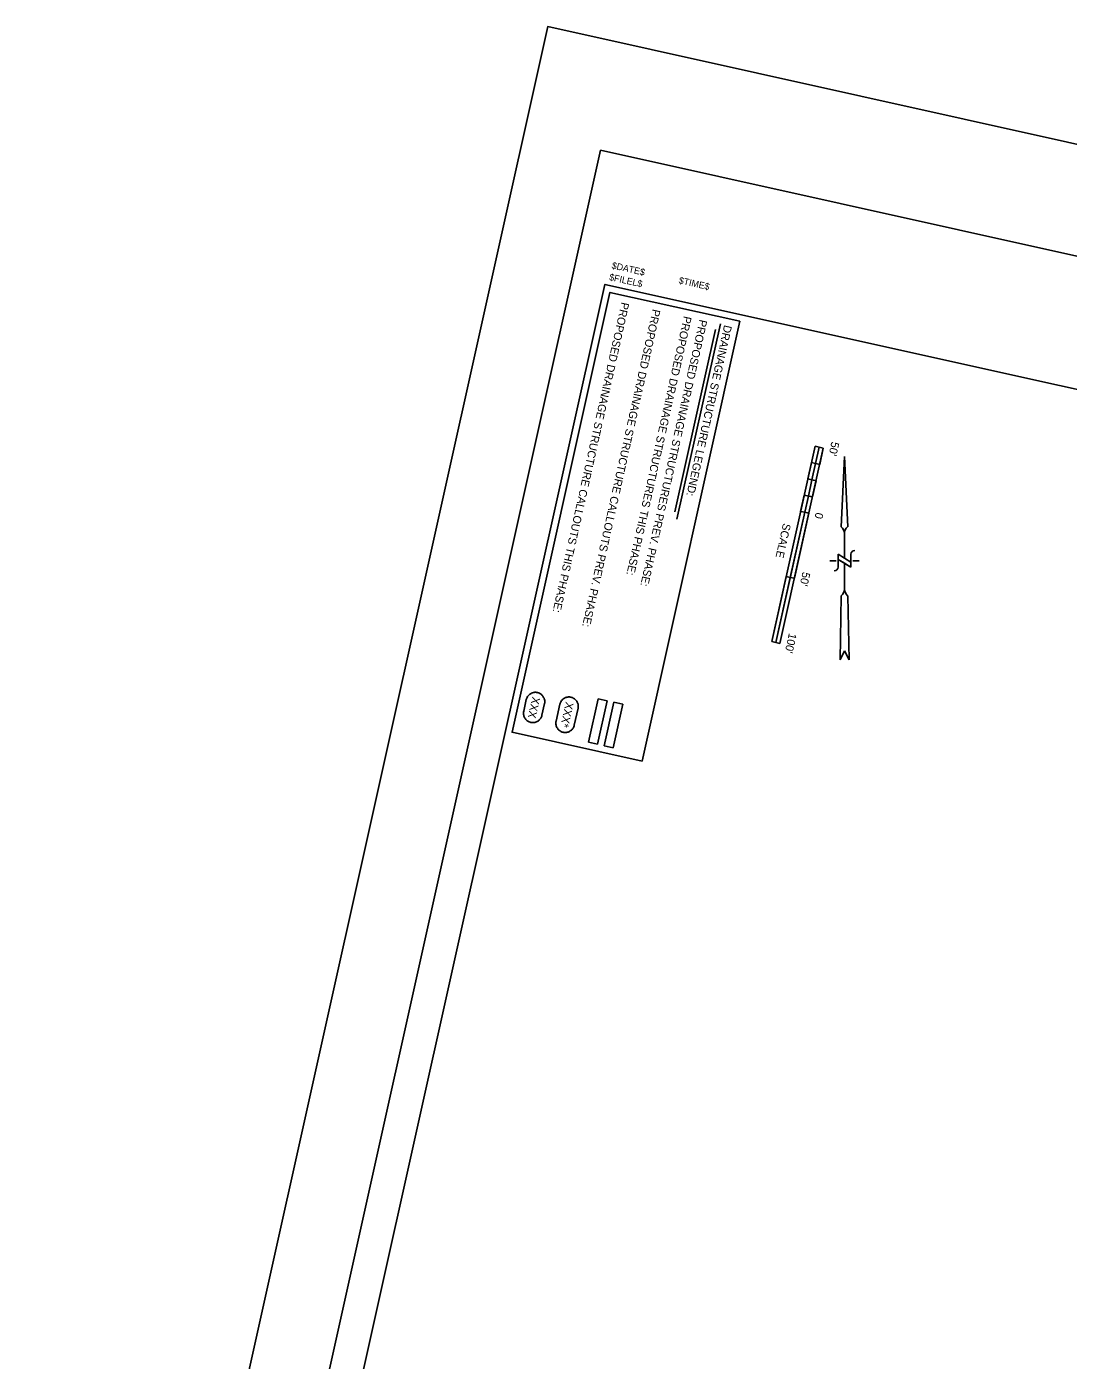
# Model space of a CAD drawing. Extents: x 2149822 to 2151384, y 143568 to 145586.
# Drawn here: x 2149822 to 2150603, y 144586 to 145586 of the extents above; entities that cross this region are included whole.
import ezdxf

# ---------------------------------------------------------------- set-up
doc = ezdxf.new("R2010")
doc.units = 0
for name, color, linetype in [('INR_Tracking', 7, 'Continuous'), ('PR_Storm_Conc_Drop_Inlet', 7, 'Continuous'), ('PR_Storm_Conc_Pipe', 7, 'Continuous'), ('PR_Storm_Conc_Pipe_PH1B', 7, 'Continuous'), ('PR_Storm_MH', 7, 'Continuous'), ('PR_Storm_Txt', 7, 'Continuous'), ('PR_Storm_Txt_PH1B', 7, 'Continuous'), ('SHT_Plot_Shape_Full', 7, 'Continuous'), ('SHT_Plot_Shape_Half', 7, 'Continuous'), ('SHT_Plot_Stamp', 7, 'Continuous')]:
    doc.layers.add(name, color=color, linetype=linetype)

msp = doc.modelspace()

# ---------------------------------------------------------------- linework, layer by layer
at = {"layer": 'INR_Tracking'}
msp.add_lwpolyline([(2149913.6, 143855.3), (2150255.5, 145392.7), (2151280.5, 145164.8), (2150938.6, 143627.3)], close=True, dxfattribs=at)
at = {"layer": 'PR_Storm_Conc_Drop_Inlet'}
for p, q in [((2150413.2, 145271.3), (2150380.6, 145124.9)), ((2150419.3, 145269.9), (2150386.7, 145123.5)), ((2150419.3, 145269.9), (2150413.2, 145271.3)), ((2150416.2, 145270.6), (2150413.5, 145258.4)), ((2150416.2, 145270.6), (2150413.5, 145258.4)), ((2150419.3, 145269.9), (2150416.2, 145270.6)), ((2150416.6, 145257.7), (2150419.3, 145269.9)), ((2150410.5, 145259.1), (2150407.8, 145246.9)), ((2150416.6, 145257.7), (2150410.5, 145259.1)), ((2150413.5, 145258.4), (2150410.5, 145259.1)), ((2150413.5, 145258.4), (2150410.8, 145246.2)), ((2150410.8, 145246.2), (2150413.5, 145258.4)), ((2150413.5, 145258.4), (2150416.6, 145257.7)), ((2150413.9, 145245.5), (2150407.8, 145246.9)), ((2150413.9, 145245.5), (2150407.8, 145246.9)), ((2150407.8, 145246.9), (2150410.8, 145246.2)), ((2150410.8, 145246.2), (2150408.1, 145234)), ((2150410.8, 145246.2), (2150408.1, 145234)), ((2150413.9, 145245.5), (2150410.8, 145246.2)), ((2150411.1, 145233.3), (2150413.9, 145245.5)), ((2150405, 145234.7), (2150402.3, 145222.5)), ((2150411.1, 145233.3), (2150405, 145234.7)), ((2150408.1, 145234), (2150405, 145234.7)), ((2150408.1, 145234), (2150405.4, 145221.8)), ((2150405.4, 145221.8), (2150408.1, 145234)), ((2150408.1, 145234), (2150411.1, 145233.3)), ((2150405.4, 145221.8), (2150383.7, 145124.2)), ((2150405.4, 145221.8), (2150394.5, 145173)), ((2150402.3, 145222.5), (2150405.4, 145221.8)), ((2150402.3, 145222.5), (2150405.4, 145221.8)), ((2150405.4, 145221.8), (2150408.4, 145221.1)), ((2150408.4, 145221.1), (2150405.4, 145221.8)), ((2150397.6, 145172.3), (2150408.4, 145221.1)), ((2150391.5, 145173.7), (2150380.6, 145124.9)), ((2150383.7, 145124.2), (2150394.5, 145173)), ((2150391.5, 145173.7), (2150394.5, 145173)), ((2150394.5, 145173), (2150391.5, 145173.7)), ((2150394.5, 145173), (2150397.6, 145172.3)), ((2150394.5, 145173), (2150397.6, 145172.3)), ((2150383.7, 145124.2), (2150380.6, 145124.9)), ((2150380.6, 145124.9), (2150383.7, 145124.2)), ((2150386.7, 145123.5), (2150383.7, 145124.2))]:
    msp.add_line(p, q, dxfattribs=at)
at = {"layer": 'PR_Storm_Conc_Pipe'}
for p, q in [((2150250.4, 145082), (2150243.2, 145049.3)), ((2150257.3, 145080.5), (2150250.4, 145082)), ((2150250, 145047.8), (2150257.3, 145080.5)), ((2150250, 145047.8), (2150243.2, 145049.3))]:
    msp.add_line(p, q, dxfattribs=at)
at = {"layer": 'PR_Storm_Conc_Pipe_PH1B'}
for p, q in [((2150262.2, 145079.4), (2150254.9, 145046.7)), ((2150261.7, 145045.1), (2150269, 145077.9)), ((2150269, 145077.9), (2150262.2, 145079.4)), ((2150261.7, 145045.1), (2150254.9, 145046.7))]:
    msp.add_line(p, q, dxfattribs=at)
at = {"layer": 'PR_Storm_MH'}
for p, q in [((2150432.8, 145210.8), (2150435.2, 145263.7)), ((2150435.2, 145263.7), (2150432.8, 145210.8)), ((2150435.2, 145263.7), (2150437.6, 145210.8)), ((2150437.6, 145210.8), (2150435.2, 145263.7)), ((2150435.2, 145187.4), (2150435.2, 145206.1)), ((2150428.9, 145185.5), (2150424.2, 145185.5)), ((2150440, 145184.5), (2150430.4, 145190.3)), ((2150430.4, 145190.3), (2150440, 145184.5)), ((2150430.4, 145190.3), (2150430.4, 145180.7)), ((2150435.2, 145187.4), (2150430.4, 145190.3)), ((2150430.4, 145190.3), (2150430.4, 145186.5)), ((2150440, 145180.7), (2150430.4, 145186.5)), ((2150440, 145184.5), (2150435.2, 145187.4)), ((2150435.2, 145163.9), (2150435.2, 145183.6)), ((2150440, 145190.3), (2150440, 145180.7)), ((2150440, 145180.7), (2150440, 145184.5)), ((2150446.2, 145185.5), (2150441.4, 145185.5)), ((2150431.9, 145111.1), (2150432.8, 145159.1)), ((2150432.8, 145159.1), (2150431.9, 145111.1)), ((2150438.6, 145111.1), (2150437.6, 145159.1)), ((2150438.6, 145111.1), (2150437.6, 145159.1)), ((2150431.9, 145111.1), (2150435.2, 145117.9)), ((2150431.9, 145111.1), (2150435.2, 145117.9)), ((2150435.2, 145117.9), (2150438.6, 145111.1)), ((2150435.2, 145117.9), (2150438.6, 145111.1))]:
    msp.add_line(p, q, dxfattribs=at)
for points in [[(2150430.4, 145186.5), (2150435.2, 145183.6), (2150440, 145180.7)], [(2150435.2, 145163.9), (2150435.2, 145163.9), (2150435.2, 145163.9)]]:
    msp.add_lwpolyline(points, dxfattribs=at)
for centre, radius, start, end in [((2150429.4, 145206.1), 5.76, 0.0232, 54.4034), ((2150429.4, 145206.1), 5.76, 0.0232, 54.4034), ((2150440.9, 145206.1), 5.76, 125.6431, 180.0232), ((2150440.9, 145206.1), 5.76, 125.6431, 180.0232), ((2150442.9, 145190.3), 2.88, 90.0232, 180.0232), ((2150427.5, 145180.7), 2.88, 270.0232, 0.0232), ((2150426.8, 145165.1), 8.43, 314.9799, 352.4421), ((2150426.8, 145165.1), 8.43, 314.9799, 352.0822), ((2150443.5, 145165.1), 8.43, 187.6043, 225.0665), ((2150443.5, 145165.1), 8.43, 187.9642, 225.0665)]:
    msp.add_arc(centre, radius, start, end, dxfattribs=at)
at = {"layer": 'PR_Storm_Txt'}
for p, q in [((2150342.2, 145363.2), (2150309.6, 145216.7)), ((2150338.4, 145358.9), (2150308, 145222.2))]:
    msp.add_line(p, q, dxfattribs=at)
msp.add_lwpolyline([(2150356.8, 145365.1), (2150283.4, 145035.2), (2150186, 145056.9), (2150259.3, 145386.7)], close=True, dxfattribs=at)
for points in [[(2150196.6, 145081.3), (2150196.8, 145081.9), (2150197, 145082.5), (2150197.2, 145083), (2150197.5, 145083.6), (2150197.9, 145084.1), (2150198.3, 145084.5), (2150198.7, 145084.9), (2150199.2, 145085.3), (2150199.7, 145085.7), (2150200.2, 145086), (2150200.8, 145086.3), (2150201.3, 145086.5), (2150201.9, 145086.6), (2150202.5, 145086.7), (2150203.1, 145086.8), (2150203.7, 145086.8), (2150204.3, 145086.7), (2150204.9, 145086.6), (2150204.9, 145086.6), (2150205.5, 145086.5), (2150206.1, 145086.3), (2150206.7, 145086), (2150207.2, 145085.7), (2150207.7, 145085.3), (2150208.2, 145084.9), (2150208.6, 145084.5), (2150209, 145084), (2150209.3, 145083.5), (2150209.6, 145083), (2150209.9, 145082.5), (2150210.1, 145081.9), (2150210.3, 145081.3), (2150210.4, 145080.7), (2150210.4, 145080.1), (2150210.4, 145079.5), (2150210.4, 145078.9), (2150210.3, 145078.3)], [(2150208.3, 145069.6), (2150208.2, 145069), (2150208, 145068.4), (2150207.7, 145067.8), (2150207.4, 145067.3), (2150207, 145066.8), (2150206.6, 145066.3), (2150206.2, 145065.9), (2150205.7, 145065.5), (2150205.2, 145065.2), (2150204.7, 145064.9), (2150204.2, 145064.6), (2150203.6, 145064.4), (2150203, 145064.2), (2150202.4, 145064.1), (2150201.8, 145064.1), (2150201.2, 145064.1), (2150200.6, 145064.1), (2150200, 145064.2), (2150200, 145064.2), (2150199.4, 145064.4), (2150198.8, 145064.6), (2150198.3, 145064.9), (2150197.7, 145065.2), (2150197.2, 145065.5), (2150196.8, 145065.9), (2150196.3, 145066.4), (2150195.9, 145066.8), (2150195.6, 145067.3), (2150195.3, 145067.8), (2150195, 145068.4), (2150194.8, 145069), (2150194.7, 145069.6), (2150194.5, 145070.2), (2150194.5, 145070.8), (2150194.5, 145071.4), (2150194.6, 145072), (2150194.7, 145072.6)], [(2150194.7, 145072.6), (2150196.6, 145081.3)], [(2150210.3, 145078.3), (2150208.3, 145069.6)]]:
    msp.add_lwpolyline(points, dxfattribs=at)
at = {"layer": 'PR_Storm_Txt_PH1B'}
for points in [[(2150221.7, 145077.8), (2150221.9, 145078.4), (2150222.1, 145079), (2150222.4, 145079.5), (2150222.7, 145080.1), (2150223, 145080.6), (2150223.4, 145081), (2150223.8, 145081.5), (2150224.3, 145081.9), (2150224.8, 145082.2), (2150225.3, 145082.5), (2150225.9, 145082.8), (2150226.5, 145083), (2150227.1, 145083.1), (2150227.7, 145083.2), (2150228.3, 145083.3), (2150228.9, 145083.3), (2150229.5, 145083.2), (2150230.1, 145083.1), (2150230.1, 145083.1), (2150230.7, 145083), (2150231.2, 145082.8), (2150231.8, 145082.5), (2150232.3, 145082.2), (2150232.8, 145081.9), (2150233.3, 145081.5), (2150233.7, 145081), (2150234.1, 145080.6), (2150234.5, 145080.1), (2150234.8, 145079.5), (2150235, 145079), (2150235.2, 145078.4), (2150235.4, 145077.8), (2150235.5, 145077.2), (2150235.6, 145076.6), (2150235.6, 145076), (2150235.5, 145075.4), (2150235.4, 145074.8)], [(2150218.9, 145065.2), (2150221.7, 145077.8)], [(2150235.4, 145074.8), (2150232.6, 145062.2)], [(2150232.6, 145062.2), (2150232.4, 145061.6), (2150232.2, 145061), (2150232, 145060.5), (2150231.7, 145059.9), (2150231.3, 145059.4), (2150230.9, 145059), (2150230.5, 145058.5), (2150230, 145058.1), (2150229.5, 145057.8), (2150229, 145057.5), (2150228.4, 145057.2), (2150227.9, 145057), (2150227.3, 145056.9), (2150226.7, 145056.7), (2150226.1, 145056.7), (2150225.4, 145056.7), (2150224.8, 145056.7), (2150224.2, 145056.9), (2150224.2, 145056.9), (2150223.6, 145057), (2150223.1, 145057.2), (2150222.5, 145057.5), (2150222, 145057.8), (2150221.5, 145058.1), (2150221, 145058.5), (2150220.6, 145059), (2150220.2, 145059.4), (2150219.9, 145059.9), (2150219.5, 145060.5), (2150219.3, 145061), (2150219.1, 145061.6), (2150218.9, 145062.2), (2150218.8, 145062.8), (2150218.8, 145063.4), (2150218.8, 145064), (2150218.8, 145064.6), (2150218.9, 145065.2)]]:
    msp.add_lwpolyline(points, dxfattribs=at)
at = {"layer": 'SHT_Plot_Shape_Full'}
msp.add_lwpolyline([(2151384.1, 145325.5), (2150993.4, 143568.4), (2149822, 143828.9), (2150212.7, 145586)], close=True, dxfattribs=at)
at = {"layer": 'SHT_Plot_Shape_Half'}
msp.add_lwpolyline([(2151326, 145254.5), (2150957, 143595.1), (2149883.3, 143833.8), (2150252.3, 145493.3)], close=True, dxfattribs=at)

# ---------------------------------------------------------------- texts
at = {"layer": 'PR_Storm_Conc_Drop_Inlet'}
for s, p in [("50'", (2150425.5, 145275.1)), ('SCALE', (2150389.2, 145213.9)), ('0', (2150413.7, 145222)), ("50'", (2150403.8, 145177.4)), ("100'", (2150393.6, 145131.5))]:
    msp.add_text(s, height=6, rotation=257.4638, dxfattribs=at).set_placement(p)
at = {"layer": 'PR_Storm_Txt'}
for s, p in [('PROPOSED DRAINAGE STRUCTURE CALLOUTS THIS PHASE:', (2150268, 145379.7)), ('PROPOSED DRAINAGE STRUCTURE CALLOUTS PREV. PHASE:', (2150291.4, 145374.5)), ('PROPOSED DRAINAGE STRUCTURES THIS PHASE:', (2150314.8, 145369.3)), ('PROPOSED DRAINAGE STRUCTURES PREV. PHASE:', (2150326.5, 145366.7)), ('DRAINAGE STRUCTURE LEGEND:', (2150345, 145362.6)), ('XXX', (2150201.2, 145083.8))]:
    msp.add_text(s, height=6, rotation=257.4638, dxfattribs=at).set_placement(p)
at = {"layer": 'PR_Storm_Txt_PH1B'}
msp.add_text('XXX*', height=6, rotation=257.4638, dxfattribs=at).set_placement((2150226.3, 145079.9))
at = {"layer": 'SHT_Plot_Stamp'}
for s, p in [('$DATE$', (2150260.3, 145404.7)), ('$FILEL$', (2150258.4, 145396)), ('$TIME$', (2150310.6, 145393.5))]:
    msp.add_text(s, height=5, rotation=347.4638, dxfattribs=at).set_placement(p)

doc.saveas('drawing.dxf')
